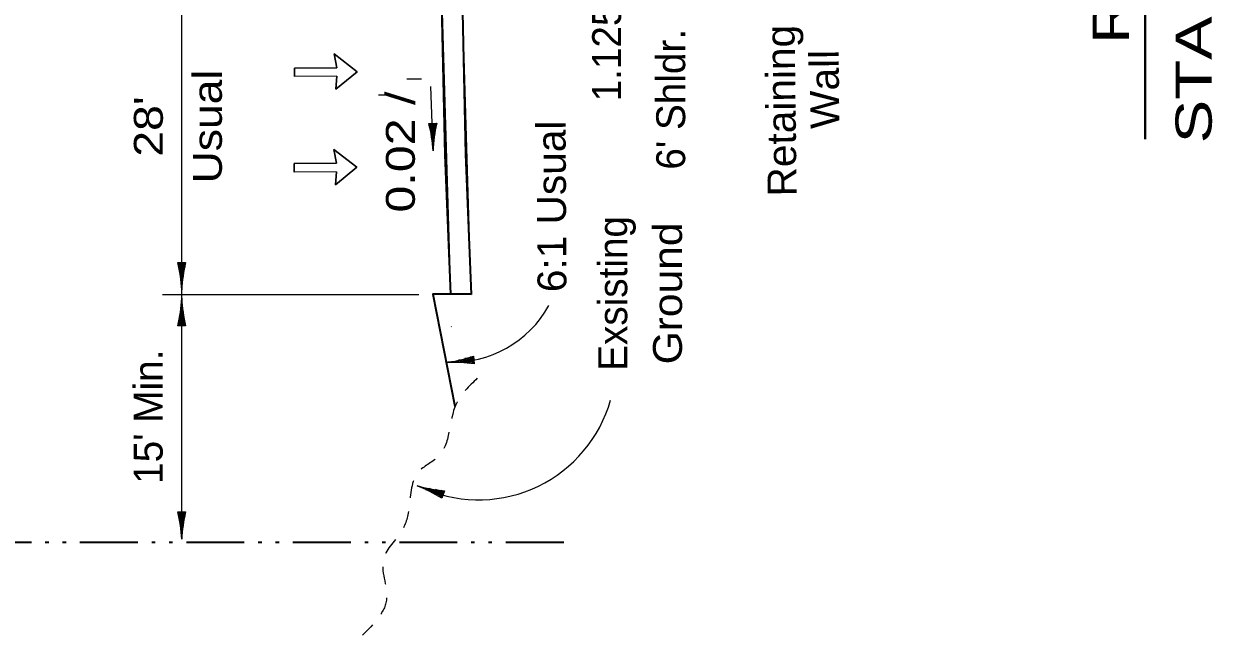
# Model space of a CAD drawing. Extents: x 2363427 to 2368559, y 6957299 to 6980140.
# Drawn here: x 2366171 to 2366746, y 6965131 to 6965427 of the extents above; entities that cross this region are included whole.
import ezdxf
from ezdxf.enums import TextEntityAlignment as Align

# ---------------------------------------------------------------- set-up
doc = ezdxf.new("R2010")
doc.units = 0
doc.header["$LTSCALE"] = 5.6
doc.linetypes.add('DASH_DOUBLE_DOT', pattern=[9.2, 5, -1.2, 0.3, -1.2, 0.3, -1.2])
doc.linetypes.add('SHORT_DASHED', pattern=[2.7, 1.5, -1.2])
for name, color, linetype, lineweight in [('1', 7, 'Continuous', 13), ('3', 7, 'Continuous', 35), ('4', 7, 'Continuous', 13), ('40', 7, 'Continuous', 35), ('6', 7, 'Continuous', 13), ('8', 7, 'Continuous', 13)]:
    doc.layers.add(name, color=color, linetype=linetype, lineweight=lineweight)

msp = doc.modelspace()

# ---------------------------------------------------------------- linework, layer by layer
at = {"layer": '1'}
for p, q in [((2366374.176, 6965198.761), (2366362.229, 6965202.651)), ((2366374.022, 6965198.286), (2366365.835, 6965200.951)), ((2366374.331, 6965199.237), (2366367.342, 6965201.512)), ((2366373.867, 6965197.811), (2366369.244, 6965199.315)), ((2366374.486, 6965199.712), (2366370.42, 6965201.036)), ((2366373.712, 6965197.335), (2366371.448, 6965198.072)), ((2366374.64, 6965200.187), (2366373.134, 6965200.679)), ((2366374.749, 6965200.521), (2366373.564, 6965196.879))]:
    msp.add_line(p, q, dxfattribs=at)
for centre, radius, start, end in [((2366378.654, 6965316.138), 53.448, 267.78918, 330.86437), ((2366391.306, 6965262.443), 66.35, 247.49469, 344.14967), ((2366335.766, 6965135.348), 72.212, 58.43843, 69.12448), ((2366380.418, 6965272.51), 72.212, 254.81159, 265.49764)]:
    msp.add_arc(centre, radius, start, end, dxfattribs=at)
at = {"layer": '1', "linetype": 'SHORT_DASHED'}
msp.add_spline([(2366390.672, 6965254.903), (2366380.425, 6965242.469), (2366371.642, 6965216.869), (2366362.128, 6965209.553), (2366357.736, 6965192.731), (2366354.076, 6965181.027), (2366345.294, 6965167.861), (2366346.758, 6965148.113), (2366335.047, 6965130.559)], degree=3, dxfattribs=at)
at = {"layer": '3'}
for p, q in [((2366382.764, 6965464.861), (2366384.99, 6965363.296)), ((2366384.99, 6965363.358), (2366387.719, 6965295.453)), ((2366387.714, 6965295.623), (2366377.711, 6965295.623))]:
    msp.add_line(p, q, dxfattribs=at)
at = {"layer": '3', "linetype": 'DASH_DOUBLE_DOT'}
msp.add_line((2366432.49, 6965175.413), (2365932.627, 6965175.413), dxfattribs=at)
at = {"layer": '3', "lineweight": 13}
msp.add_lwpolyline([(2366377.711, 6965295.623), (2366387.719, 6965295.453), (2366382.764, 6965464.861), (2366372.762, 6965464.861)], close=True, dxfattribs=at)
at = {"layer": '3'}
for points in [[(2366372.762, 6965464.861), (2366374.992, 6965363.096), (2366377.711, 6965295.623)], [(2366377.711, 6965295.623), (2366369.088, 6965295.623), (2366379.79, 6965241.443)]]:
    msp.add_lwpolyline(points, dxfattribs=at)
at = {"layer": '4', "lineweight": 40}
msp.add_line((2366713.786, 6965370.713), (2366713.786, 6965746.309), dxfattribs=at)
at = {"layer": '4'}
for p, q in [((2366247.636, 6965348.773), (2366247.636, 6965451.735)), ((2366369.306, 6965364.991), (2366368.232, 6965396.166)), ((2366367.18, 6965378.271), (2366371.01, 6965378.331)), ((2366367.53, 6965378.275), (2366367.556, 6965376.691)), ((2366368.03, 6965378.283), (2366368.098, 6965374.007)), ((2366368.53, 6965378.291), (2366368.646, 6965370.943)), ((2366369.03, 6965378.299), (2366369.23, 6965365.737)), ((2366369.53, 6965378.307), (2366369.666, 6965369.699)), ((2366370.03, 6965378.315), (2366370.108, 6965373.455)), ((2366370.53, 6965378.323), (2366370.568, 6965375.943)), ((2366247.636, 6965188.499), (2366247.636, 6965348.773)), ((2366245.72, 6965311.007), (2366249.55, 6965311.007)), ((2366246.07, 6965311.007), (2366246.07, 6965309.422)), ((2366246.57, 6965311.007), (2366246.57, 6965306.731)), ((2366247.07, 6965311.007), (2366247.07, 6965303.657)), ((2366247.57, 6965311.007), (2366247.57, 6965298.443)), ((2366248.07, 6965311.007), (2366248.07, 6965302.397)), ((2366248.57, 6965311.007), (2366248.57, 6965306.145)), ((2366249.07, 6965311.007), (2366249.07, 6965308.625)), ((2366362.304, 6965295.315), (2366238.384, 6965295.315)), ((2366247.2, 6965280.322), (2366247.2, 6965288.931)), ((2366247.7, 6965280.322), (2366247.7, 6965292.886)), ((2366246.2, 6965280.322), (2366246.2, 6965282.703)), ((2366246.7, 6965280.322), (2366246.7, 6965285.184)), ((2366248.2, 6965280.322), (2366248.2, 6965287.672)), ((2366248.7, 6965280.322), (2366248.7, 6965284.599)), ((2366249.55, 6965280.322), (2366245.72, 6965280.322)), ((2366249.2, 6965280.322), (2366249.2, 6965281.907)), ((2366378.056, 6965279.917), (2366378.124, 6965279.771)), ((2366245.72, 6965190.347), (2366249.55, 6965190.347)), ((2366246.07, 6965190.347), (2366246.07, 6965188.762)), ((2366246.57, 6965190.347), (2366246.57, 6965186.071)), ((2366247.07, 6965190.347), (2366247.07, 6965182.997)), ((2366247.57, 6965190.347), (2366247.57, 6965177.783)), ((2366248.07, 6965190.347), (2366248.07, 6965181.737)), ((2366248.57, 6965190.347), (2366248.57, 6965185.485)), ((2366249.07, 6965190.347), (2366249.07, 6965187.965))]:
    msp.add_line(p, q, dxfattribs=at)
at = {"layer": '4', "lineweight": 25}
for p, q in [((2366356.548, 6965399.863), (2366363.739, 6965399.863)), ((2366349.357, 6965392.024), (2366342.819, 6965392.024))]:
    msp.add_line(p, q, dxfattribs=at)
at = {"layer": '4'}
for centre, start, end in [((2366297.248, 6965360.266), 3.7522, 14.43825), ((2366441.477, 6965362.553), 167.37903, 178.06508), ((2366175.512, 6965294.114), 2.84356, 13.52961), ((2366319.759, 6965294.114), 166.47039, 177.15644), ((2366175.512, 6965297.216), 346.47039, 357.15644), ((2366319.759, 6965297.216), 182.84356, 193.52961), ((2366175.512, 6965173.454), 2.84356, 13.52961), ((2366319.759, 6965173.454), 166.47039, 177.15644)]:
    msp.add_arc(centre, 72.212, start, end, dxfattribs=at)
at = {"layer": '40', "lineweight": 13}
for p, q in [((2366322.698, 6965401.1), (2366302.193, 6965400.906)), ((2366322.514, 6965354.902), (2366302.01, 6965354.706))]:
    msp.add_line(p, q, dxfattribs=at)
for points in [[(2366322.698, 6965401.1), (2366322.165, 6965394.786), (2366332.553, 6965403.32), (2366321.453, 6965411.924), (2366322.66, 6965405.196)], [(2366322.66, 6965405.196), (2366302.155, 6965405), (2366302.193, 6965400.906)], [(2366322.514, 6965354.902), (2366321.982, 6965348.586), (2366332.37, 6965357.122), (2366321.27, 6965365.724), (2366322.478, 6965358.996)], [(2366322.478, 6965358.996), (2366301.972, 6965358.802), (2366302.01, 6965354.706)]]:
    msp.add_lwpolyline(points, dxfattribs=at)
at = {"layer": '6'}
for p, q in [((2366388.807, 6965265.323), (2366387.229, 6965265.175)), ((2366388.774, 6965265.671), (2366389.133, 6965261.859)), ((2366388.948, 6965263.829), (2366376.438, 6965262.651)), ((2366388.994, 6965263.332), (2366380.422, 6965262.524)), ((2366388.9, 6965264.327), (2366381.583, 6965263.639)), ((2366389.041, 6965262.834), (2366384.2, 6965262.377)), ((2366388.854, 6965264.825), (2366384.596, 6965264.424)), ((2366389.088, 6965262.336), (2366386.718, 6965262.113))]:
    msp.add_line(p, q, dxfattribs=at)
for centre, start, end in [((2366365.372, 6965333.987), 278.2236, 288.90965), ((2366378.896, 6965190.375), 81.85043, 92.53648)]:
    msp.add_arc(centre, 72.212, start, end, dxfattribs=at)
at = {"layer": '8'}
for points in [[(2366332.553, 6965403.32), (2366322.165, 6965394.786), (2366322.698, 6965401.1), (2366302.193, 6965400.906), (2366302.155, 6965405), (2366322.66, 6965405.196), (2366321.453, 6965411.924)], [(2366332.37, 6965357.122), (2366321.982, 6965348.586), (2366322.514, 6965354.902), (2366302.01, 6965354.706), (2366301.972, 6965358.802), (2366322.478, 6965358.996), (2366321.27, 6965365.724)]]:
    msp.add_lwpolyline(points, close=True, dxfattribs=at)

# ---------------------------------------------------------------- texts
at = {"layer": '4'}
for s, height, rotation, width, p in [('STA 49+00 TO STA 63+00', 17.5, 90, 1.35, (2366746.037, 6965558.303)), ('RAMP SBFR - 820S', 17.5, 90, 1.3, (2366705.941, 6965554.652)), ('Retaining', 14, 90.665, 1.05, (2366544.696, 6965384.514)), ('Wall', 14, 90.665, 1.05, (2366565.692, 6965394.822)), ('Usual', 14, 90, 1.15, (2366267.069, 6965376.777)), ('0.02 /', 14, 90, 1.25, (2366360.458, 6965364.425)), ("28'", 14, 90, 1.2, (2366238.499, 6965376.777)), ('6:1 Usual', 14, 90.307, 1.05, (2366433.593, 6965338.149)), ('Ground', 14, 90, 1.1, (2366489.706, 6965295.986))]:
    msp.add_text(s, height=height, rotation=rotation, dxfattribs=dict(at, width=width)).set_placement(p, align=Align.CENTER)
for s, p in [("1.125' ", (2366460.247, 6965416.753)), ("6' Shldr.", (2366491.257, 6965389.953)), ('Exsisting', (2366463.206, 6965295.987)), ("15' Min.", (2366238.422, 6965236.321))]:
    msp.add_text(s, height=14, rotation=90, dxfattribs=at).set_placement(p, align=Align.CENTER)

doc.saveas('drawing.dxf')
